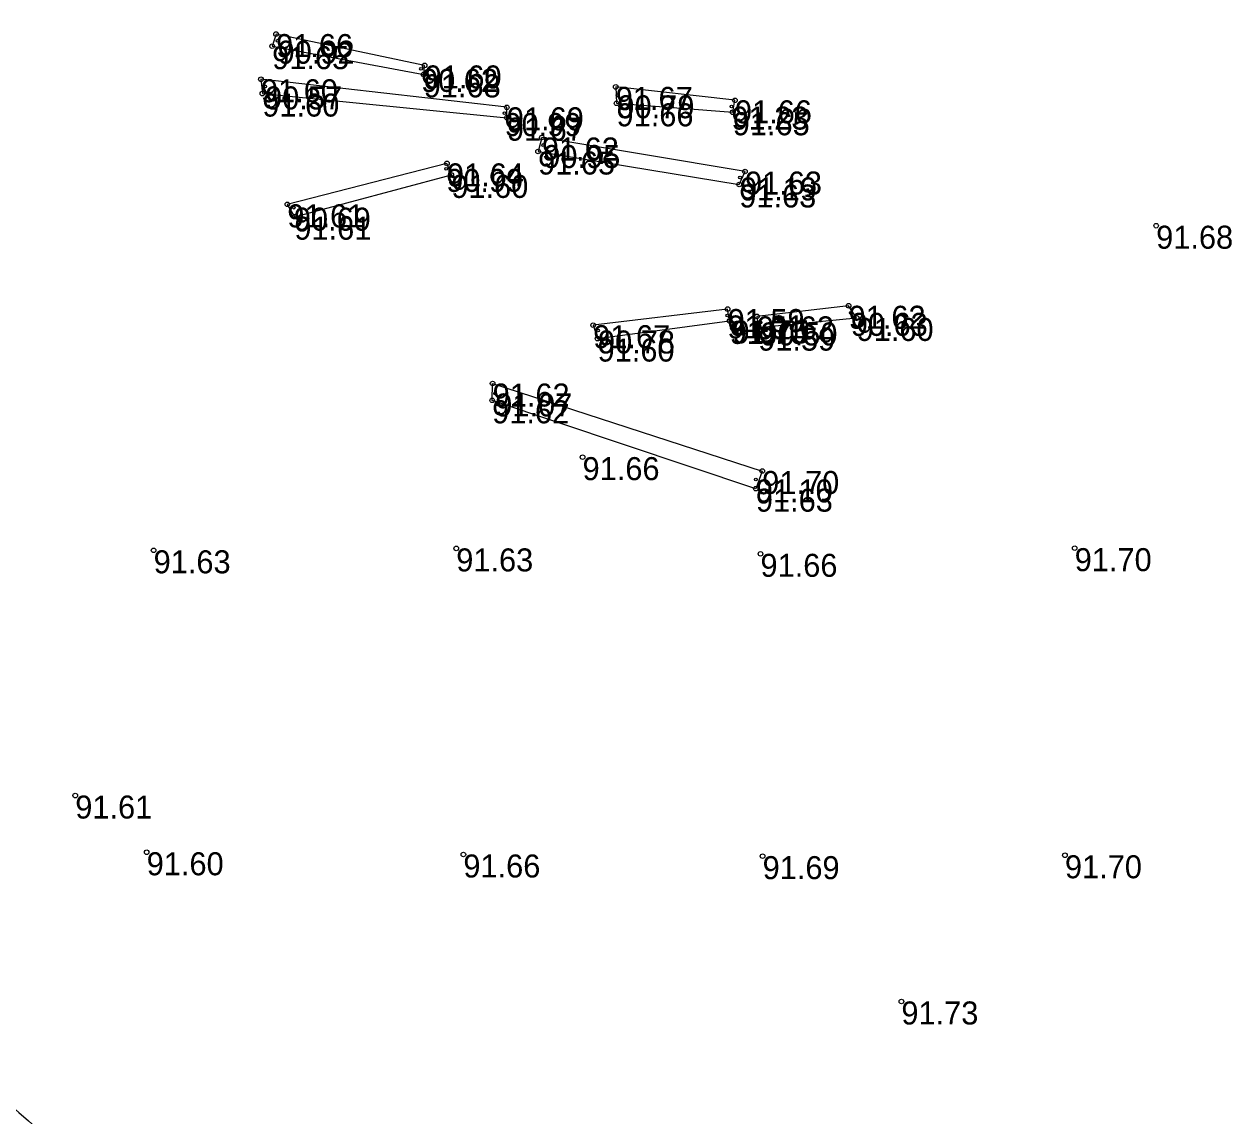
# Model space of a CAD drawing. Extents: x 316000 to 728450, y 314368 to 726000.
# Drawn here: x 726019.5 to 726217, y 315372.4 to 315550.4 of the extents above; entities that cross this region are included whole.
import ezdxf

# ---------------------------------------------------------------- set-up
doc = ezdxf.new("R2010")
doc.units = 0
for name, color, linetype in [('HIDG_ELEM_####_####_#', 7, 'Continuous'), ('HIDG_GRAV_####_####_#', 7, 'Continuous'), ('RELJ_AATZ_####_TKST_#', 7, 'Continuous'), ('RELJ_ELEM_####_####_#', 7, 'Continuous'), ('RELJ_HORZ_PAMT_####_#', 7, 'Continuous'), ('RELJ_NOGA_####_####_#', 7, 'Continuous')]:
    doc.layers.add(name, color=color, linetype=linetype)

msp = doc.modelspace()

# ---------------------------------------------------------------- linework, layer by layer
at = {"layer": 'HIDG_ELEM_####_####_#'}
for centre in [(726060.81, 315547.67), (726084.19, 315543.07), (726058.77, 315540.22), (726116.21, 315538.77), (726097.79, 315535.87), (726134.78, 315536.93), (726104.12, 315530.66), (726088.29, 315526.77), (726136.19, 315525.38), (726063.46, 315520.45), (726134.12, 315502.88), (726139.52, 315501.74), (726154.24, 315503.3), (726113.03, 315500.43), (726096.29, 315490.16), (726138.75, 315476.15)]:
    msp.add_circle(centre, 0.225, dxfattribs=at)
at = {"layer": 'HIDG_GRAV_####_####_#'}
for points in [[(726060.56, 315548.75), (726059.92, 315546.78), (726084.62, 315542.18), (726084.77, 315543.64), (726060.56, 315548.75)], [(726058.09, 315541.38), (726058.32, 315539.05), (726098.18, 315535.12), (726098.18, 315536.81), (726058.09, 315541.38)], [(726115.93, 315540.14), (726116.05, 315537.46), (726135, 315536), (726135.36, 315537.95), (726115.93, 315540.14)], [(726103.88, 315531.89), (726103.27, 315529.6), (726136.06, 315524.23), (726137, 315526.34), (726103.88, 315531.89)], [(726062.39, 315520.99), (726063.54, 315518.98), (726089.13, 315525.79), (726088.41, 315527.67), (726062.39, 315520.99)], [(726112.25, 315501.29), (726112.96, 315499.11), (726134.49, 315501.99), (726134.17, 315503.92), (726112.25, 315501.29)], [(726138.94, 315502.73), (726139.15, 315500.89), (726155.19, 315502.47), (726153.88, 315504.46), (726138.94, 315502.73)], [(726139.81, 315477.52), (726138.77, 315474.64), (726095.78, 315489.04), (726095.86, 315491.78), (726139.81, 315477.52)]]:
    msp.add_lwpolyline(points, dxfattribs=at)
at = {"layer": 'RELJ_ELEM_####_####_#'}
for centre in [(726060.56, 315548.75), (726059.92, 315546.78), (726084.77, 315543.64), (726058.09, 315541.38), (726084.62, 315542.18), (726058.32, 315539.05), (726115.93, 315540.14), (726116.05, 315537.46), (726135.36, 315537.95), (726098.18, 315536.81), (726098.18, 315535.12), (726135, 315536), (726103.88, 315531.89), (726103.27, 315529.6), (726088.41, 315527.67), (726089.13, 315525.79), (726137, 315526.34), (726136.06, 315524.23), (726062.39, 315520.99), (726063.54, 315518.98), (726204.02, 315517.51), (726134.17, 315503.92), (726153.88, 315504.46), (726134.49, 315501.99), (726138.94, 315502.73), (726155.19, 315502.47), (726112.25, 315501.29), (726139.15, 315500.89), (726112.96, 315499.11), (726095.86, 315491.78), (726095.78, 315489.04), (726110.52, 315479.78), (726139.81, 315477.52), (726138.77, 315474.64), (726040.6, 315464.59), (726089.93, 315464.9), (726139.52, 315464.02), (726190.74, 315464.94), (726027.83, 315424.61), (726039.47, 315415.36), (726091.09, 315415), (726139.87, 315414.73), (726189.15, 315414.87), (726162.49, 315391.04)]:
    msp.add_circle(centre, 0.375, dxfattribs=at)
at = {"layer": 'RELJ_HORZ_PAMT_####_#'}
msp.add_spline([(726116.34, 315699.09), (726105.94, 315702.69), (726040.13, 315715), (725990.82, 315710.42), (725942.03, 315708.25), (725920.28, 315706.77), (725880.37, 315714.51), (725859.05, 315708.68), (725859.05, 315672.66), (725851.26, 315613.97), (725853.47, 315568.9), (725841, 315555.79), (725885.56, 315509.63), (725935.94, 315461.49), (725983.42, 315406.25), (726032.86, 315360.51), (726082.85, 315311.19), (726122.23, 315248.76), (726137.05, 315229.29), (726180.19, 315183.1), (726194.52, 315168.27), (726211.91, 315146.93), (726212.51, 315143.16)], degree=3, dxfattribs=at)
at = {"layer": 'RELJ_NOGA_####_####_#'}
for points in [[(726259.12, 315084.51), (726262.72, 315089.26), (726261.56, 315090.84), (726260.2, 315092.42), (726257.29, 315095.53), (726218.91, 315136.38), (726180.31, 315176.84), (726128.67, 315229.97), (726063.7, 315298.11), (725999.9, 315366.09), (725937.21, 315432.09), (725876.35, 315495.23), (725810.58, 315563.08), (725744.7, 315632.91)], [(725740.86, 315626.98), (725805.54, 315558.12), (725870.39, 315491.15), (725932.8, 315426.8), (725994.98, 315360.84), (726059.66, 315292.12), (726075.75, 315275.46), (726092.08, 315259.04), (726108.47, 315242.67), (726124.69, 315226.14), (726193.27, 315154.03), (726250.06, 315092.6), (726256.32, 315085.83), (726258.82, 315084.29), (726259.12, 315084.51)]]:
    msp.add_spline(points, degree=3, dxfattribs=at)

# ---------------------------------------------------------------- texts
at = {"layer": 'RELJ_AATZ_####_TKST_#'}
for s, p in [('91.66', (726060.56, 315545)), ('90.92', (726060.81, 315543.92)), ('91.65', (726059.92, 315543.03)), ('91.60', (726084.77, 315539.89)), ('91.60', (726058.09, 315537.63)), ('90.62', (726084.19, 315539.32)), ('91.68', (726084.62, 315538.43)), ('90.57', (726058.77, 315536.47)), ('91.67', (726115.93, 315536.39)), ('91.60', (726058.32, 315535.3)), ('91.66', (726116.05, 315533.71)), ('90.79', (726116.21, 315535.02)), ('91.66', (726135.36, 315534.2)), ('90.99', (726097.79, 315532.12)), ('91.69', (726098.18, 315533.06)), ('91.23', (726134.78, 315533.18)), ('91.65', (726135, 315532.25)), ('91.67', (726098.18, 315531.37)), ('91.62', (726103.88, 315528.14)), ('91.65', (726103.27, 315525.85)), ('90.95', (726104.12, 315526.91)), ('91.64', (726088.41, 315523.92)), ('90.99', (726088.29, 315523.02)), ('91.60', (726089.13, 315522.04)), ('91.63', (726137, 315522.59)), ('91.63', (726136.06, 315520.48)), ('91.19', (726136.19, 315521.63)), ('91.61', (726062.39, 315517.24)), ('90.69', (726063.46, 315516.7)), ('91.61', (726063.54, 315515.23)), ('91.68', (726204.02, 315513.76)), ('91.59', (726134.17, 315500.17)), ('91.62', (726153.88, 315500.71)), ('91.01', (726134.12, 315499.13)), ('91.70', (726134.49, 315498.24)), ('91.75', (726134.97, 315498.32)), ('91.62', (726138.94, 315498.98)), ('90.63', (726154.24, 315499.55)), ('91.60', (726155.19, 315498.72)), ('91.67', (726112.25, 315497.54)), ('90.78', (726113.03, 315496.68)), ('91.59', (726139.15, 315497.14)), ('90.50', (726139.52, 315497.99)), ('91.60', (726112.96, 315495.36)), ('91.62', (726095.86, 315488.03)), ('91.07', (726096.29, 315486.41)), ('91.62', (726095.78, 315485.29)), ('91.66', (726110.52, 315476.03)), ('91.10', (726138.75, 315472.4)), ('91.70', (726139.81, 315473.77)), ('91.63', (726138.77, 315470.89)), ('91.63', (726040.6, 315460.84)), ('91.63', (726089.93, 315461.15)), ('91.70', (726190.74, 315461.19)), ('91.66', (726139.52, 315460.27)), ('91.61', (726027.83, 315420.86)), ('91.60', (726039.47, 315411.61)), ('91.66', (726091.09, 315411.25)), ('91.69', (726139.87, 315410.98)), ('91.70', (726189.15, 315411.12)), ('91.73', (726162.49, 315387.29))]:
    msp.add_text(s, height=3.75, dxfattribs=at).set_placement(p)

doc.saveas('drawing.dxf')
